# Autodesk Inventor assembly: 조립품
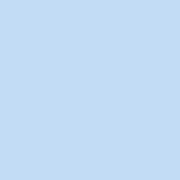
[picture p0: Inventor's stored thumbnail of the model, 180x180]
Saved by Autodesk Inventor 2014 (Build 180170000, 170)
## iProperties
Created: 2026-05
Part Number: 조립품
Document SubType Name: Assembly
Designer: dg
Author: dg
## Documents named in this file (1)
- C:\Users\dg\Desktop\760503v1007\조립품.iam
